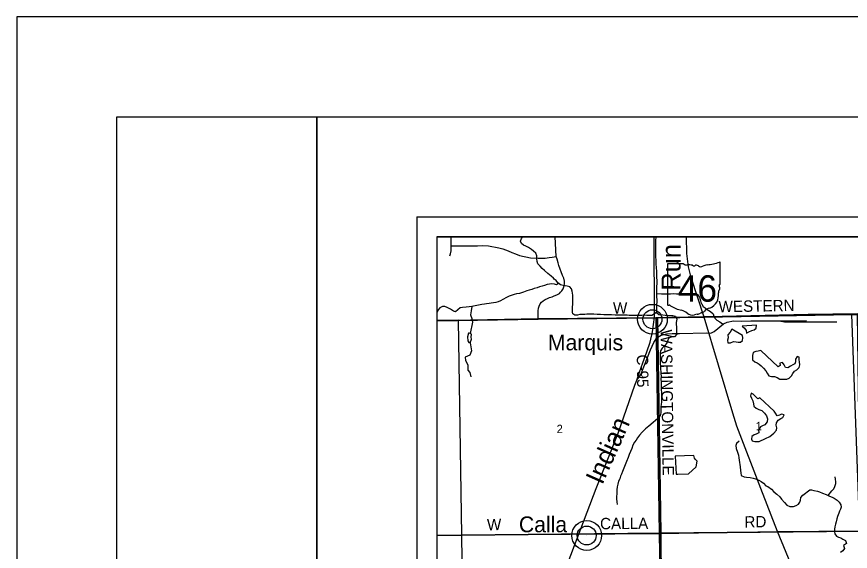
# Model space of a CAD drawing. Extents: x 0 to 36.9, y 0 to 22.
# Drawn here: x 0 to 4.166, y 19.328 to 22 of the extents above; entities that cross this region are included whole.
import ezdxf

# ---------------------------------------------------------------- set-up
doc = ezdxf.new("R2010")
doc.units = 0
for name, color, linetype in [('Default', 7, 'Continuous'), ('GM_X_County_Road', 7, 'Continuous'), ('GM_X_County_Road_Text', 7, 'Continuous'), ('GM_X_Minor_Lake', 7, 'Continuous'), ('GM_X_Minor_River', 7, 'Continuous'), ('GM_X_Minor_River_Text', 7, 'Continuous'), ('GM_X_Rail_Line', 7, 'Continuous'), ('GM_X_Section', 7, 'Continuous'), ('GM_X_Section_Text', 7, 'Continuous'), ('GM_X_State_Location', 7, 'Continuous'), ('GM_X_State_Route', 7, 'Continuous'), ('GM_X_State_Shield', 7, 'Continuous'), ('GM_X_Township_Road', 7, 'Continuous'), ('GM_X_Unincorporated', 7, 'Continuous'), ('GM_X_Unincorporated_Location', 7, 'Continuous'), ('GM_X_Unincorporated_Text', 7, 'Continuous'), ('SH_Border', 7, 'Continuous'), ('SH_Cut_Line', 7, 'Continuous'), ('SH_Data', 7, 'Continuous')]:
    doc.layers.add(name, color=color, linetype=linetype)

msp = doc.modelspace()

# ---------------------------------------------------------------- linework, layer by layer
at = {"layer": 'Default'}
for points in [[(2.1, 20.4814), (2.1, 19.4072), (2.2245, 19.4084), (2.2075, 20.4833), (2.1432, 20.4822)], [(2.1, 19.4072), (2.1, 18.4183), (2.2385, 18.4199), (2.2245, 19.4084)]]:
    msp.add_lwpolyline(points, close=True, dxfattribs=at)
at = {"layer": 'GM_X_County_Road'}
for p in [(3.1944, 20.4947), (2.1, 19.4086)]:
    msp.add_line(p, (3.21, 19.4177), dxfattribs=at)
for points in [[(2.1, 20.4796), (2.6056, 20.4892), (3.1944, 20.4947), (3.4357, 20.499), (4.1744, 20.5113), (4.1972, 20.5117)], [(3.21, 19.4177), (3.802, 19.4268), (4.2126, 19.4308)], [(3.21, 19.4177), (3.2275, 18.4294), (3.2285, 17.4352), (3.232, 16.893), (3.2368, 16.4429)]]:
    msp.add_lwpolyline(points, dxfattribs=at)
at = {"layer": 'GM_X_Minor_Lake'}
for points in [[(3.6246, 20.4536), (3.6365, 20.4436), (3.6447, 20.4312), (3.6464, 20.4187), (3.6588, 20.4253), (3.6732, 20.4324), (3.686, 20.4349), (3.6961, 20.4438), (3.6963, 20.4578)], [(3.6963, 20.4578), (3.6246, 20.4536)], [(2.2723, 20.4138), (2.2627, 20.4186), (2.2581, 20.4193), (2.2528, 20.3994), (2.2546, 20.3797), (2.2593, 20.3726), (2.2665, 20.3708)], [(2.2665, 20.3708), (2.2725, 20.3877), (2.2719, 20.3991), (2.2723, 20.4138)], [(3.574, 20.438), (3.5647, 20.4242), (3.5536, 20.4099), (3.5549, 20.3959), (3.5521, 20.3833), (3.5531, 20.3701), (3.5664, 20.3699), (3.5815, 20.3762), (3.5948, 20.3745), (3.605, 20.3732), (3.6164, 20.3734), (3.6265, 20.3819), (3.6282, 20.3948), (3.6265, 20.407)], [(3.6265, 20.407), (3.574, 20.438)], [(3.7192, 20.3317), (3.7056, 20.3285), (3.6939, 20.3264), (3.6811, 20.3216), (3.6771, 20.3075), (3.6773, 20.2976), (3.6767, 20.2851), (3.6894, 20.2758), (3.7001, 20.271), (3.7097, 20.264), (3.7197, 20.2558), (3.7321, 20.2442), (3.7444, 20.2307), (3.7507, 20.2179), (3.7585, 20.2047), (3.7726, 20.2019), (3.7867, 20.2018), (3.8, 20.1967), (3.8142, 20.1882), (3.8252, 20.188), (3.8491, 20.1884), (3.8597, 20.1939), (3.8713, 20.2054), (3.8783, 20.2166), (3.8872, 20.2289), (3.8989, 20.2351), (3.9097, 20.2467), (3.9133, 20.2604), (3.9119, 20.2748), (3.9094, 20.2847), (3.91, 20.298), (3.9004, 20.3024), (3.8927, 20.2886), (3.8914, 20.2753), (3.8892, 20.2657), (3.8787, 20.2606), (3.8663, 20.2536), (3.8535, 20.2446), (3.8417, 20.2471), (3.8347, 20.2599), (3.8273, 20.2727), (3.8144, 20.2683), (3.815, 20.2566), (3.8052, 20.2503)], [(3.8052, 20.2503), (3.7192, 20.3317)], [(3.7136, 20.0961), (3.7035, 20.0903), (3.6915, 20.1019), (3.6799, 20.1135), (3.67, 20.1186), (3.6668, 20.106), (3.6727, 20.0943), (3.6793, 20.0808), (3.6822, 20.066), (3.6836, 20.0539), (3.6955, 20.0438), (3.7089, 20.0376), (3.7234, 20.0317), (3.7373, 20.0183), (3.7462, 20.0059), (3.7518, 19.99), (3.7509, 19.9756), (3.7379, 19.9606), (3.7273, 19.9555), (3.7168, 19.9496), (3.7072, 19.9346), (3.7093, 19.921), (3.6954, 19.9135), (3.6852, 19.9099), (3.6743, 19.9018), (3.6715, 19.8896), (3.6758, 19.8798), (3.688, 19.8777), (3.6994, 19.8771), (3.7096, 19.8777), (3.721, 19.8813), (3.7323, 19.8864), (3.7428, 19.8915), (3.7631, 19.9025), (3.774, 19.9106), (3.7841, 19.918), (3.7964, 19.9334), (3.7989, 19.9452), (3.7956, 19.9585), (3.7973, 19.9706), (3.8058, 19.9837), (3.8182, 19.9923), (3.828, 19.9977), (3.835, 20.01), (3.8224, 20.0143), (3.8122, 20.0085), (3.8005, 20.0056), (3.7923, 20.0184), (3.7861, 20.0293)], [(3.7861, 20.0293), (3.7136, 20.0961)], [(3.2898, 19.804), (3.2955, 19.7137), (3.3046, 19.7131), (3.357, 19.7151), (3.3951, 19.7506), (3.4004, 19.7788), (3.3922, 19.7867), (3.3868, 19.7942), (3.3843, 19.8067)], [(3.3843, 19.8067), (3.2898, 19.804)]]:
    msp.add_lwpolyline(points, dxfattribs=at)
at = {"layer": 'GM_X_Minor_River'}
for points in [[(3.1971, 20.5223), (3.1742, 20.5063), (3.1617, 20.5069), (3.1484, 20.5074), (3.1378, 20.5076), (3.1245, 20.5074), (3.1101, 20.5068), (3.0888, 20.5065), (3.0736, 20.507), (3.0615, 20.5075), (3.0512, 20.5081), (3.0387, 20.5083), (3.0273, 20.5081), (3.0174, 20.5084), (3.0038, 20.5081), (2.9912, 20.5083), (2.9726, 20.5095), (2.9593, 20.5101), (2.9487, 20.5103), (2.9343, 20.5104), (2.9179, 20.5113), (2.9012, 20.5122), (2.8841, 20.5126), (2.8666, 20.5131), (2.8499, 20.5128), (2.8386, 20.5123), (2.8291, 20.5125), (2.8146, 20.5119), (2.8025, 20.509), (2.7896, 20.5092), (2.7797, 20.5144), (2.7772, 20.5242), (2.777, 20.5382), (2.7776, 20.5485), (2.7789, 20.5641), (2.7798, 20.5786), (2.7795, 20.5934), (2.7789, 20.6082), (2.778, 20.618), (2.7767, 20.6286), (2.7731, 20.64), (2.7638, 20.6501), (2.7501, 20.6529), (2.7402, 20.6543), (2.7303, 20.656), (2.7181, 20.6596), (2.7038, 20.6704), (2.6957, 20.6816), (2.6857, 20.6883), (2.6822, 20.6932), (2.671, 20.7029), (2.6537, 20.717), (2.6383, 20.7316), (2.6252, 20.7424), (2.6167, 20.754), (2.6051, 20.7645), (2.6003, 20.7766), (2.599, 20.7902), (2.5995, 20.8043), (2.594, 20.8182), (2.5828, 20.8276), (2.5724, 20.8361), (2.5574, 20.8458), (2.5444, 20.8531), (2.5322, 20.8586), (2.5226, 20.8668), (2.5178, 20.8774), (2.5229, 20.8908), (2.5272, 20.9)], [(3.1932, 20.9), (3.1931, 20.8804), (3.1918, 20.8671), (3.1917, 20.8523), (3.1919, 20.842), (3.1928, 20.8318), (3.1931, 20.8143), (3.1929, 20.8048), (3.1933, 20.779), (3.1939, 20.7653), (3.1958, 20.7445), (3.1968, 20.7278), (3.1974, 20.7111), (3.1982, 20.6666), (3.198, 20.6522), (3.1978, 20.6412), (3.1977, 20.6279), (3.1976, 20.6108), (3.1982, 20.5743), (3.1977, 20.5603), (3.1971, 20.5462), (3.197, 20.5325), (3.1971, 20.5223), (3.2091, 20.5118), (3.2289, 20.5095), (3.241, 20.5082), (3.2539, 20.5073), (3.2661, 20.5075), (3.279, 20.5073), (3.2916, 20.5033), (3.2983, 20.4882), (3.2959, 20.4719), (3.2957, 20.4616), (3.297, 20.4495), (3.298, 20.4388), (3.2967, 20.4259), (3.2984, 20.4134), (3.2868, 20.4003), (3.2743, 20.4001), (3.2596, 20.3934), (3.2545, 20.3831), (3.2483, 20.3678), (3.2367, 20.3558), (3.2263, 20.3431), (3.2181, 20.3304), (3.216, 20.3205), (3.2158, 20.3103), (3.2164, 20.2962), (3.2162, 20.2848), (3.2162, 20.2666), (3.2168, 20.2522), (3.2178, 20.2385), (3.2191, 20.2252), (3.2193, 20.2146), (3.2199, 20.2028), (3.2197, 20.1892), (3.22, 20.174), (3.2206, 20.1611), (3.2212, 20.1478), (3.221, 20.1337), (3.2215, 20.1242), (3.2217, 20.1147), (3.2223, 20.1022), (3.2221, 20.0882), (3.2216, 20.0756), (3.2207, 20.0619)], [(2.708, 20.6672), (2.6976, 20.6604), (2.688, 20.6625), (2.6747, 20.6642), (2.663, 20.6636), (2.6512, 20.6612), (2.638, 20.6568), (2.6263, 20.6535), (2.6134, 20.6499), (2.6002, 20.6451), (2.5866, 20.6415), (2.5738, 20.6375), (2.5606, 20.6335), (2.5496, 20.6295), (2.5323, 20.6239), (2.5221, 20.6207), (2.5119, 20.6175), (2.4971, 20.6142), (2.4865, 20.611), (2.4767, 20.6086), (2.4612, 20.6038), (2.4469, 20.5971), (2.4296, 20.5865), (2.4176, 20.5803), (2.4055, 20.5751), (2.3945, 20.5723), (2.3821, 20.5702), (2.3718, 20.5685), (2.3616, 20.5672), (2.3472, 20.5643), (2.3374, 20.5626), (2.3241, 20.5613), (2.2995, 20.5563), (2.2749, 20.5521), (2.2605, 20.55), (2.2454, 20.5486), (2.2283, 20.5472), (2.2158, 20.5451), (2.205, 20.5354), (2.1922, 20.5257), (2.1827, 20.5286), (2.1673, 20.5386), (2.1516, 20.5474), (2.139, 20.5522), (2.1284, 20.5516), (2.1152, 20.5457), (2.1066, 20.5353), (2.1019, 20.5238), (2.1, 20.5212)], [(3.1976, 20.6169), (3.2226, 20.615), (3.2336, 20.6144), (3.2507, 20.6143), (3.267, 20.6153), (3.2829, 20.616), (3.297, 20.6158), (3.3087, 20.6156), (3.3235, 20.6163), (3.3334, 20.616), (3.3474, 20.6159), (3.3585, 20.6157), (3.371, 20.6155), (3.3816, 20.6153), (3.3911, 20.6151), (3.401, 20.613), (3.4119, 20.5991), (3.4151, 20.587), (3.4187, 20.5737), (3.4235, 20.5628), (3.4301, 20.5515), (3.4401, 20.5445), (3.4505, 20.5367), (3.4666, 20.5267), (3.4797, 20.5155), (3.4844, 20.5038), (3.49, 20.4913), (3.4996, 20.4828), (3.5141, 20.4758), (3.5268, 20.4653)], [(2.2748, 20.5521), (2.2715, 20.5293), (2.2676, 20.5106), (2.2748, 20.4917), (2.2774, 20.4728), (2.2654, 20.4172)], [(2.2665, 20.3708), (2.2733, 20.3306), (2.2653, 20.3089), (2.2536, 20.3034), (2.2404, 20.299), (2.2425, 20.2823), (2.2547, 20.2601), (2.2551, 20.2342), (2.2637, 20.2215), (2.2697, 20.1995)], [(3.2207, 20.0619), (3.2197, 20.0513), (3.2196, 20.033), (3.2191, 20.022), (3.2181, 20.0125), (3.2145, 20.0018), (3.2047, 19.9918), (3.1931, 19.9821), (3.1804, 19.9724), (3.1583, 19.9538), (3.143, 19.9403), (3.1265, 19.9237), (3.112, 19.9082), (3.1031, 19.8948), (3.0953, 19.8844), (3.0879, 19.8733), (3.0798, 19.8583), (3.0736, 19.8423), (3.0666, 19.827), (3.0604, 19.8117), (3.055, 19.7972), (3.0473, 19.7773), (3.0408, 19.7605), (3.0346, 19.7433), (3.0277, 19.7272), (3.0225, 19.7146), (3.0182, 19.7039), (3.0138, 19.6913), (3.0079, 19.679), (3.0033, 19.6634), (3.0005, 19.65), (2.9992, 19.6363), (2.9983, 19.6173), (2.9975, 19.6014), (2.998, 19.5907), (2.9994, 19.5763), (3.0004, 19.5631)], [(3.6098, 19.878), (3.5974, 19.8675), (3.593, 19.8579), (3.5952, 19.8416), (3.6023, 19.8239), (3.6071, 19.8084), (3.6089, 19.7951), (3.6106, 19.7845), (3.6127, 19.7728), (3.6136, 19.7626), (3.6149, 19.75), (3.6175, 19.7322), (3.6188, 19.7205), (3.621, 19.7072), (3.6355, 19.701), (3.6473, 19.6993), (3.6659, 19.6966), (3.6796, 19.6945), (3.6922, 19.6909), (3.7086, 19.6847), (3.7205, 19.6773), (3.7317, 19.6688), (3.7444, 19.656), (3.7544, 19.6516), (3.7716, 19.639), (3.7836, 19.6263), (3.799, 19.6136), (3.8129, 19.6006), (3.8222, 19.5882), (3.8365, 19.5728), (3.8493, 19.559), (3.8638, 19.5531), (3.8813, 19.5523), (3.8945, 19.5571), (3.9069, 19.5633), (3.9136, 19.5737), (3.9161, 19.5836), (3.9192, 19.5974), (3.9282, 19.6096)], [(4.0552, 19.6076), (4.0735, 19.6314), (4.0832, 19.6414), (4.0891, 19.6521), (4.0934, 19.6666), (4.094, 19.6761), (4.0919, 19.6886), (4.0894, 19.7003)], [(3.9282, 19.6096), (3.963, 19.6351), (3.9725, 19.6349), (3.9839, 19.6328), (4.0018, 19.6289), (4.0117, 19.6249), (4.0263, 19.6191), (4.045, 19.6123), (4.0626, 19.6042), (4.0749, 19.5991), (4.0852, 19.594), (4.1009, 19.584), (4.1095, 19.5739), (4.1188, 19.5604), (4.1194, 19.5498), (4.1173, 19.5395), (4.1126, 19.5292), (4.1089, 19.5196), (4.1017, 19.5017), (4.0984, 19.4906), (4.0949, 19.4765), (4.0917, 19.4643), (4.0881, 19.4502), (4.0868, 19.4388), (4.0867, 19.4251), (4.0888, 19.4153), (4.0962, 19.4048), (4.1069, 19.3996), (4.1187, 19.3957), (4.1283, 19.3898), (4.1414, 19.3816), (4.1462, 19.3681), (4.1323, 19.3572), (4.136, 19.3421), (4.129, 19.3306), (4.117, 19.3231)]]:
    msp.add_lwpolyline(points, dxfattribs=at)
at = {"layer": 'GM_X_Rail_Line'}
msp.add_line((3.8101, 20.4803), (3.9475, 20.4823), dxfattribs=at)
msp.add_lwpolyline([(5.9205, 20.9), (2.1, 20.9), (2.1, 20.4802), (2.6054, 20.4898), (3.1942, 20.4953), (3.4355, 20.4995), (4.1742, 20.5119), (4.5929, 20.5183), (5.1496, 20.5295), (5.2978, 20.5324), (5.3186, 20.5329), (5.9236, 20.5446)], close=True, dxfattribs=at)
for points in [[(3.0997, 20.183), (3.1125, 20.2237), (3.1298, 20.2699), (3.1497, 20.3259), (3.1662, 20.3739), (3.1778, 20.4243), (3.1873, 20.4979), (3.1857, 20.9)], [(4.2428, 16.065), (4.2237, 16.806), (4.2214, 17.442), (4.2174, 18.4382), (4.22, 18.531), (4.2124, 19.4314), (4.2095, 19.5156), (4.1742, 20.5119), (3.4355, 20.4995), (3.1942, 20.4953), (2.6054, 20.4898), (2.1, 20.4802), (2.1, 14.4405)], [(3.0997, 20.183), (3.119, 20.2123), (3.167, 20.3346), (3.1835, 20.3716), (3.1991, 20.3949), (3.2213, 20.4087), (3.2478, 20.4155), (3.2761, 20.4173), (3.3115, 20.4172), (3.4464, 20.4195), (3.4685, 20.4192), (3.485, 20.4262), (3.5317, 20.4646), (3.5507, 20.4733), (3.5814, 20.4794), (3.6215, 20.4777), (3.6681, 20.4799), (3.8101, 20.4803)], [(3.8101, 20.4803), (3.8377, 20.4748), (4.0978, 20.4752)], [(2.7245, 19.1906), (2.8955, 19.6426), (3.0055, 19.9195), (3.0892, 20.1585), (3.0997, 20.183)]]:
    msp.add_lwpolyline(points, dxfattribs=at)
at = {"layer": 'GM_X_Section'}
for points in [[(2.7972, 20.4925), (3.2025, 20.497), (3.2188, 19.419), (2.2245, 19.4084), (2.2075, 20.4833)], [(4.1996, 20.5167), (4.2133, 19.5112), (4.212, 19.4289), (3.2188, 19.419), (3.2025, 20.497), (3.3829, 20.4998), (3.9553, 20.5131)], [(2.2245, 19.4084), (3.2188, 19.419), (3.226, 18.4277), (2.2385, 18.4199)], [(4.212, 19.4289), (4.2176, 18.508), (4.219, 18.4391), (3.226, 18.4277), (3.2188, 19.419)]]:
    msp.add_lwpolyline(points, close=True, dxfattribs=at)
at = {"layer": 'GM_X_State_Route'}
for p, q in [((3.5789, 20.0185), (3.4357, 20.499)), ((3.802, 19.4268), (3.7187, 19.6422))]:
    msp.add_line(p, q, dxfattribs=at)
for points in [[(3.4357, 20.499), (3.3712, 20.6973), (3.3568, 20.7505), (3.3489, 20.8169), (3.3475, 20.9)], [(3.7187, 19.6422), (3.5981, 19.9542), (3.5789, 20.0185)], [(4.2202, 18.5304), (4.0532, 18.8191), (4.0295, 18.8744), (3.802, 19.4268)]]:
    msp.add_lwpolyline(points, dxfattribs=at)
at = {"layer": 'GM_X_State_Shield'}
for p, q in [((3.252, 20.7618), (3.252, 20.5617)), ((3.3318, 20.7653), (3.2546, 20.7653)), ((3.5157, 20.6656), (3.5157, 20.7702)), ((3.5157, 20.6656), (3.5157, 20.6656))]:
    msp.add_line(p, q, dxfattribs=at)
for centre, radius, start, end in [((3.2551, 20.7623), 0.00305, 98.1301, 188.1301), ((3.3502, 20.7885), 0.0296, 231.6195, 271.1119), ((3.3601, 20.6529), 0.1064, 80.4867, 94.9883), ((3.3842, 20.7633), 0.00855, 219.7921, 297.1024), ((3.3968, 20.7402), 0.0178, 54.4667, 119.1411), ((3.4197, 20.7719), 0.0214, 233.8562, 294.8282), ((3.4574, 20.7042), 0.0563, 97.3462, 120.7689), ((3.4218, 21.0381), 0.2796, 275.8445, 288.9065), ((3.5128, 20.7707), 0.00294, 351.8621, 97.738), ((3.5126, 20.6652), 0.00314, 289.6038, 7.7341), ((3.5262, 20.6218), 0.0198, 136.8065, 186.9296), ((3.515, 20.6579), 0.00454, 107.944, 210.337), ((3.4861, 20.6446), 0.0273, 340.033, 23.6496), ((3.4374, 20.6084), 0.0699, 292.3089, 8.9858), ((3.2551, 20.5613), 0.00308, 171.9584, 258.3066), ((3.2555, 20.5818), 0.0235, 267.339, 280.6039), ((3.2604, 20.5502), 0.00848, 29.7484, 93.2717), ((3.3674, 20.73), 0.2019, 240.4129, 257.1985), ((3.4669, 20.5055), 0.0383, 94.4031, 142.5768), ((3.3072, 20.4718), 0.0632, 47.1842, 75.836), ((3.3755, 20.5492), 0.0401, 230.7004, 286.2918), ((3.3987, 20.48), 0.0329, 85.6951, 111.2099), ((3.4016, 20.5342), 0.0214, 268.777, 315.5493), ((3.421, 20.5148), 0.00601, 65.7517, 132.6484), ((3.4184, 20.5423), 0.0226, 282.8732, 323.2771)]:
    msp.add_arc(centre, radius, start, end, dxfattribs=at)
at = {"layer": 'GM_X_Township_Road'}
for points in [[(2.1648, 20.8045), (2.1673, 20.8143), (2.1713, 20.8304), (2.1719, 20.8553), (2.1717, 20.9)], [(2.6056, 20.4892), (2.6053, 20.5152), (2.6059, 20.5308), (2.607, 20.5427), (2.6102, 20.5531), (2.6165, 20.5649), (2.623, 20.5729), (2.6304, 20.5799), (2.6404, 20.587), (2.6529, 20.5925), (2.6626, 20.5963), (2.6751, 20.6008), (2.6866, 20.6052), (2.6991, 20.6102), (2.7118, 20.6171), (2.7183, 20.6226), (2.724, 20.6292), (2.7283, 20.6346), (2.7303, 20.6395), (2.7332, 20.6457), (2.7362, 20.6549), (2.7377, 20.6648), (2.7374, 20.6781), (2.7336, 20.6933), (2.7276, 20.7068), (2.7215, 20.7244), (2.7152, 20.7391), (2.7092, 20.757), (2.7053, 20.7702), (2.7006, 20.7881), (2.6954, 20.8021), (2.6917, 20.9)], [(2.1719, 20.8553), (2.2339, 20.8542), (2.2701, 20.8542), (2.3025, 20.8553), (2.3278, 20.8558), (2.3575, 20.8547), (2.3748, 20.852), (2.3931, 20.8488), (2.4088, 20.8456), (2.4293, 20.8396), (2.4557, 20.8294), (2.4746, 20.8223), (2.4924, 20.8142), (2.5135, 20.8067), (2.5675, 20.7948), (2.6063, 20.7927), (2.6403, 20.7932), (2.6603, 20.7959), (2.6759, 20.7981), (2.6954, 20.8021)]]:
    msp.add_lwpolyline(points, dxfattribs=at)
at = {"layer": 'GM_X_Unincorporated'}
for centre, radius in [((3.177, 20.4881), 0.0744), ((3.177, 20.4881), 0.0472), ((2.8485, 19.4073), 0.0744), ((2.8485, 19.4073), 0.0472)]:
    msp.add_circle(centre, radius, dxfattribs=at)
at = {"layer": 'GM_X_Unincorporated_Location'}
for p, q in [((3.177, 20.4881), (3.177, 20.4881)), ((2.8485, 19.4073), (2.8485, 19.4073))]:
    msp.add_line(p, q, dxfattribs=at)
at = {"layer": 'SH_Border'}
for points in [[(0.5, 21.5), (1.5, 21.5), (1.5, 0.5), (0.5, 0.5)], [(1.5, 21.5), (33.5, 21.5), (33.5, 0.5), (1.5, 0.5)]]:
    msp.add_lwpolyline(points, close=True, dxfattribs=at)
at = {"layer": 'SH_Cut_Line'}
msp.add_lwpolyline([(0, 0), (34, 0), (34, 22), (0, 22)], close=True, dxfattribs=at)
msp.add_lwpolyline([(8.9, 14.5158), (8.9, 20.9), (2.1, 20.9), (2.1, 14.4405)], dxfattribs=at)
at = {"layer": 'SH_Data'}
for p, q in [((2, 21), (9, 21)), ((2, 21), (2, 14)), ((2.1, 20.9), (2.1, 14.1)), ((2.1, 20.9), (8.9, 20.9))]:
    msp.add_line(p, q, dxfattribs=at)

# ---------------------------------------------------------------- texts
at = {"layer": 'GM_X_County_Road_Text'}
for s, height, rotation, p in [('WESTERN', 0.05682, 1.0204, (3.5078, 20.5226)), ('W', 0.0568, 0.7248, (2.9804, 20.5151)), ('WASHINGTONVILLE', 0.056818, 270.7827, (3.2181, 20.4364)), ('C-95', 0.05682, 270.6858, (3.0987, 20.3116)), ('CALLA', 0.05682, 0.412, (2.9155, 19.4384)), ('RD', 0.05682, 0.9872, (3.637, 19.4468)), ('W', 0.0568, 0.7248, (2.3504, 19.4334))]:
    msp.add_text(s, height=height, rotation=rotation, dxfattribs=at).set_placement(p)
at = {"layer": 'GM_X_Minor_River_Text'}
for s, rotation, p in [('Run', 89.9573, (3.3172, 20.6311)), ('Indian', 65.9818, (2.9263, 19.6567))]:
    msp.add_text(s, height=0.09473, rotation=rotation, dxfattribs=at).set_placement(p)
at = {"layer": 'GM_X_Section_Text'}
for s, p in [('2', (2.6982, 19.919)), ('1', (3.6928, 19.9336))]:
    msp.add_text(s, height=0.0419, rotation=0, dxfattribs=at).set_placement(p)
at = {"layer": 'GM_X_State_Location'}
msp.add_text('46', height=0.000189, rotation=0, dxfattribs=at).set_placement((3.3332, 20.6347))
for s in ['s', 'r']:
    msp.add_text(s, height=0.000189, dxfattribs=at).set_placement((3.3809, 20.6485))
at = {"layer": 'GM_X_State_Shield'}
msp.add_text('46', height=0.13184, dxfattribs=at).set_placement((3.3036, 20.5758))
at = {"layer": 'GM_X_Unincorporated_Text'}
for s, p in [('Marquis', (2.6549, 20.3327)), ('Calla', (2.5099, 19.4235))]:
    msp.add_text(s, height=0.07898, rotation=0, dxfattribs=at).set_placement(p)

doc.saveas('drawing.dxf')
